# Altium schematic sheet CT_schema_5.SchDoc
size 479 x 328 mm
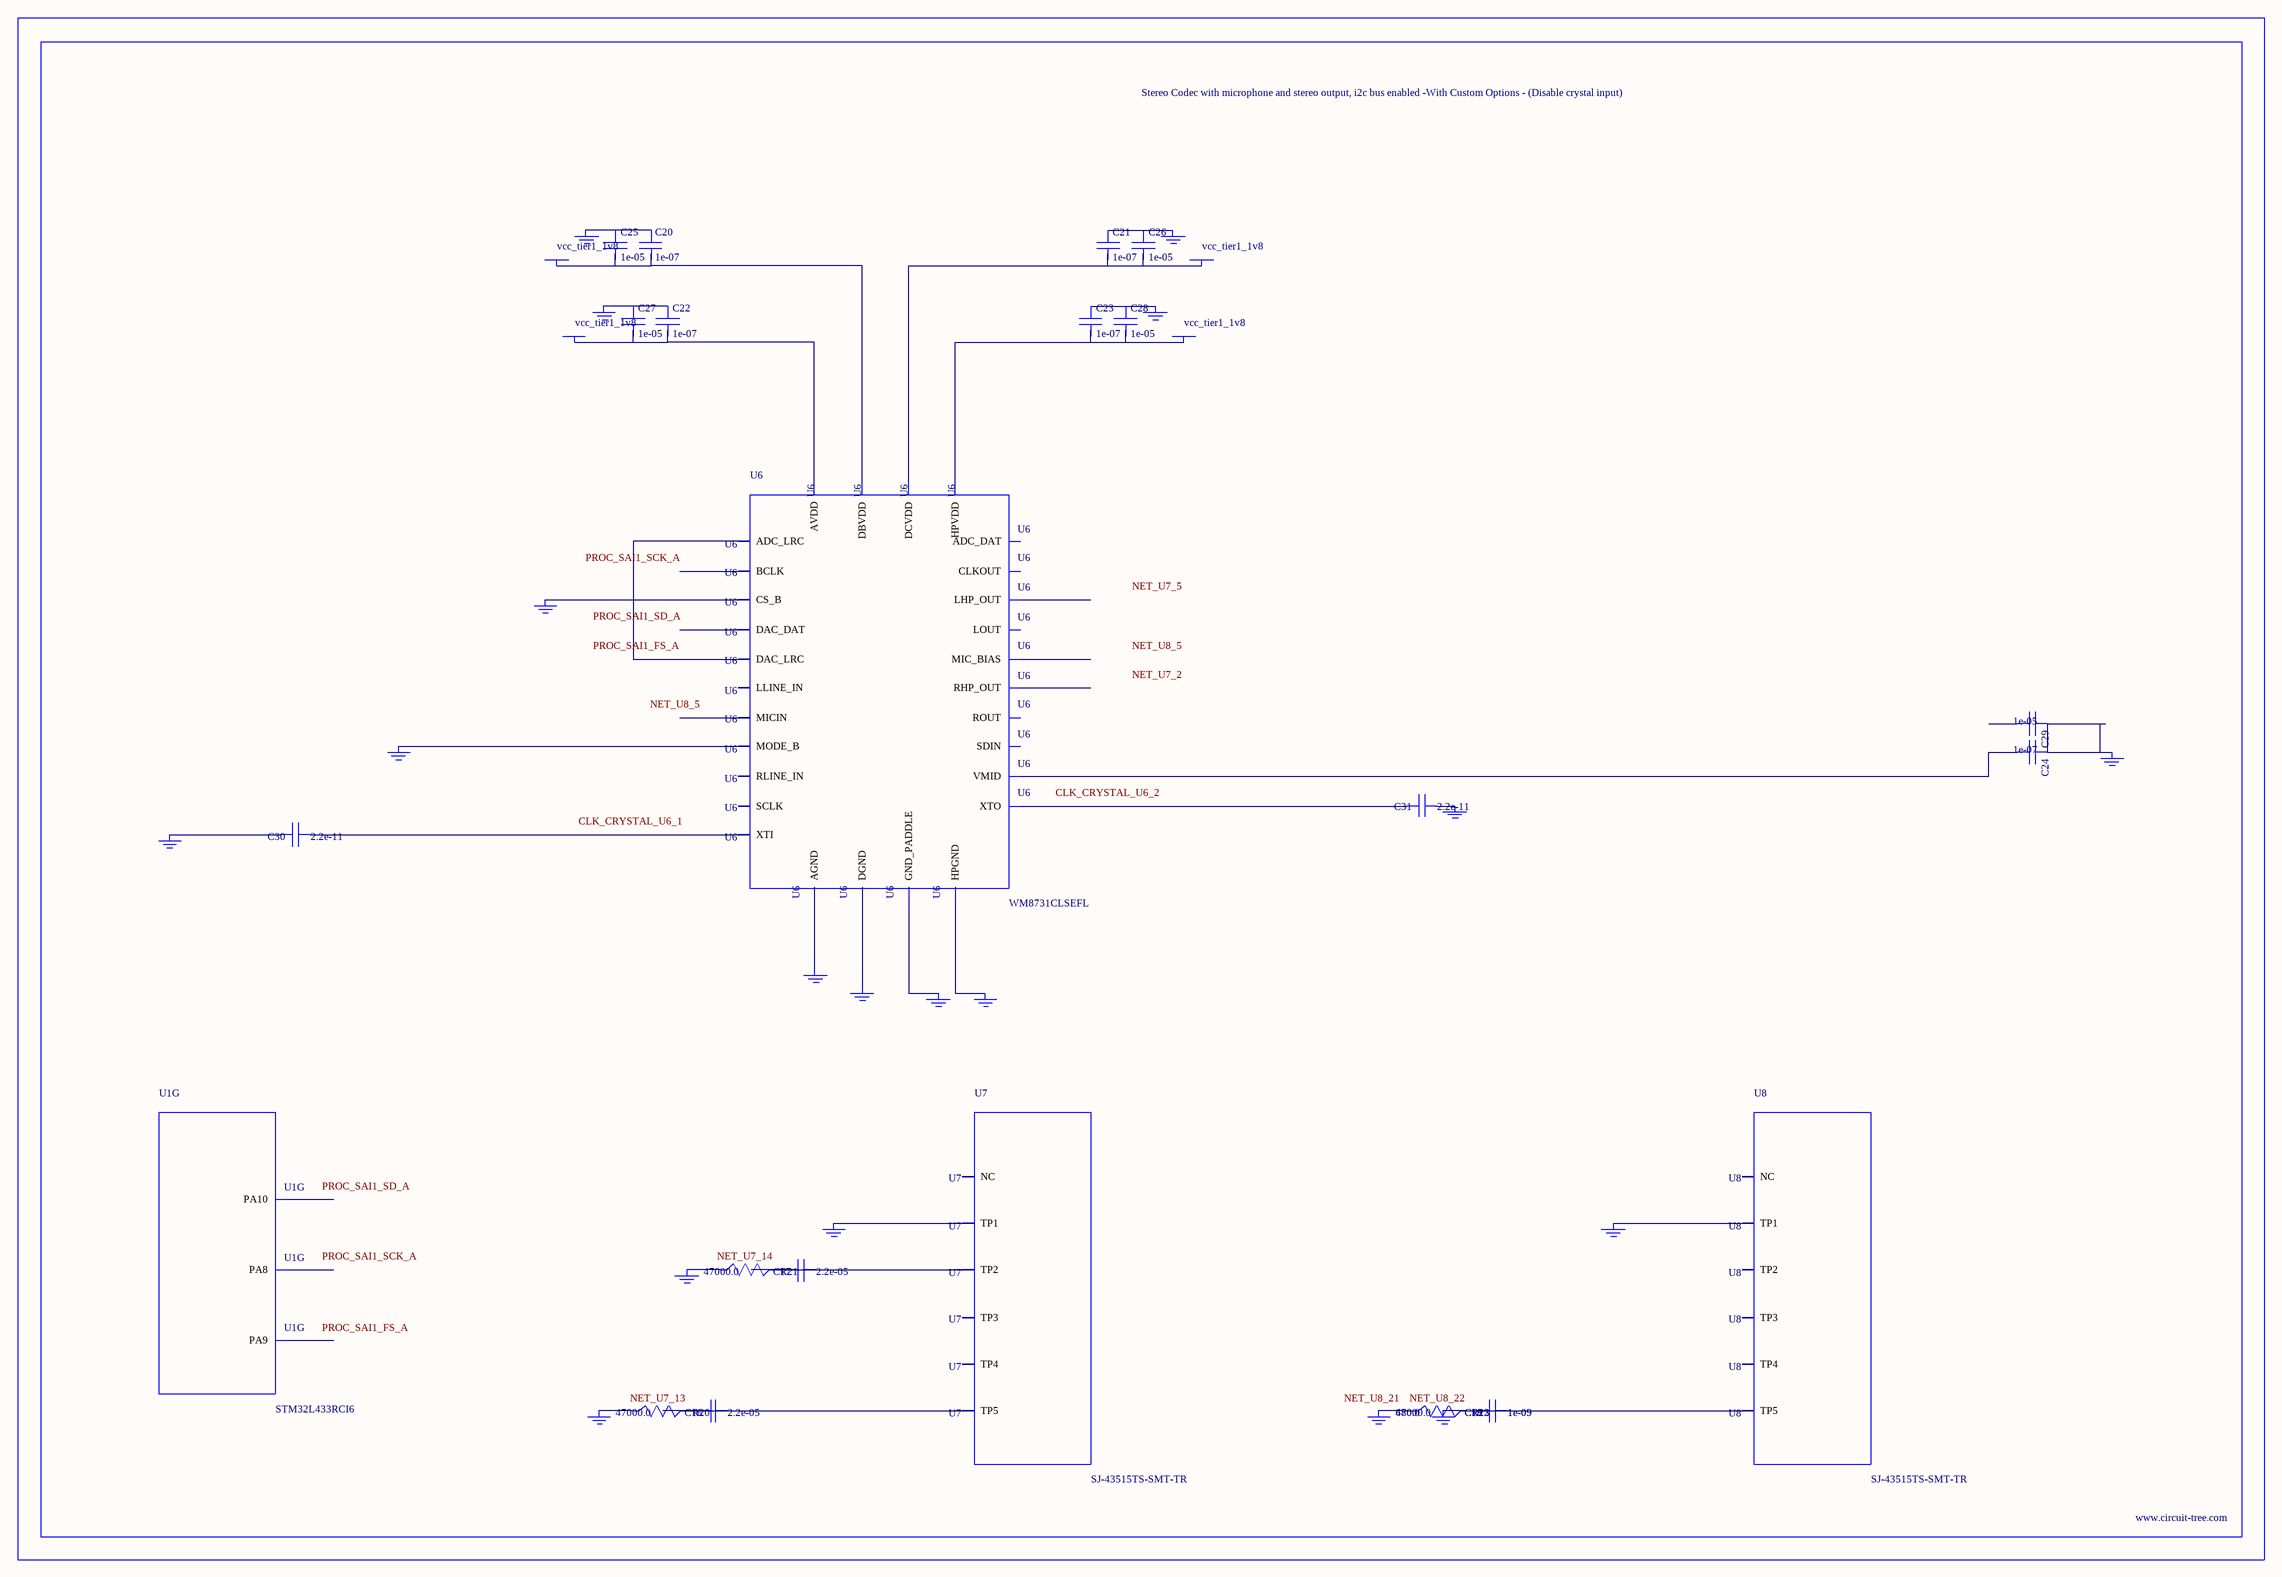
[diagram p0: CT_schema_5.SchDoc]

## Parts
BORDER4  (no value)
C16  2.2e-05  [C1210]
C17  2.2e-05  [C1210]
C18  1e-09  [C0402]
C19  1e-09  [C0402]
C20  1e-07  [C0402]
C21  1e-07  [C0402]
C22  1e-07  [C0402]
C23  1e-07  [C0402]
C24  1e-07  [C0402]
C25  1e-05  [C0805]
C26  1e-05  [C0805]
C27  1e-05  [C0805]
C28  1e-05  [C0805]
C29  1e-05  [C0805]
C30  2.2e-11  [C0402]
C31  2.2e-11  [C0402]
GND_INSTANCE_4_0  (no value)
GND_INSTANCE_4_1  (no value)
GND_INSTANCE_4_2  (no value)
GND_INSTANCE_4_3  (no value)
GND_INSTANCE_4_4  (no value)
GND_INSTANCE_4_5  (no value)
GND_INSTANCE_4_6  (no value)
GND_INSTANCE_4_7  (no value)
GND_INSTANCE_4_8  (no value)
GND_INSTANCE_4_9  (no value)
GND_INSTANCE_4_10  (no value)
GND_INSTANCE_4_11  (no value)
GND_INSTANCE_4_12  (no value)
GND_INSTANCE_4_13  (no value)
GND_INSTANCE_4_14  (no value)
GND_INSTANCE_4_15  (no value)
GND_INSTANCE_4_16  (no value)
GND_INSTANCE_4_17  (no value)
GND_INSTANCE_4_18  (no value)
POWER_INSTANCE_4_0  vcc_tier1_1v8
POWER_INSTANCE_4_1  vcc_tier1_1v8
POWER_INSTANCE_4_2  vcc_tier1_1v8
POWER_INSTANCE_4_3  vcc_tier1_1v8
R20  47000.0  [R0603]
R21  47000.0  [R0603]
R22  47000.0  [R0603]
R23  680.0  [R0603]
U1  STM32L433RCI6  [UFBGA64]  (part G of 7)
U6  WM8731CLSEFL  [QFN-28]
U7  SJ-43515TS-SMT-TR  [SJ-43515TS-SMT-TR]
U8  SJ-43515TS-SMT-TR  [SJ-43515TS-SMT-TR]

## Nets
NetC16_1: C16.1 C16.2 R20.2 U7.5(TP5)
NetC17_1: C17.1 C17.2 R21.2 U7.2(TP2)
NetC18_1: C18.1 C18.2 C19.1 C19.2 GND_INSTANCE_4_18.0(GND) R22.2 R23.2 U8.5(TP5)
NetC20_1: C20.1 C25.1 GND_INSTANCE_4_3.0(GND)
NetC20_2: C20.2 C25.2 POWER_INSTANCE_4_1.0(PWR) U6.5(DBVDD)
NetC21_1: C21.1 C26.1 GND_INSTANCE_4_2.0(GND)
NetC21_2: C21.2 C26.2 POWER_INSTANCE_4_0.0(PWR) U6.3(DCVDD)
NetC22_1: C22.1 C27.1 GND_INSTANCE_4_6.0(GND)
NetC22_2: C22.2 C27.2 POWER_INSTANCE_4_3.0(PWR) U6.18(AVDD)
NetC23_1: C23.1 C28.1 GND_INSTANCE_4_4.0(GND)
NetC23_2: C23.2 C28.2 POWER_INSTANCE_4_2.0(PWR) U6.12(HPVDD)
NetC24_1: C24.1 C29.1 GND_INSTANCE_4_7.0(GND)
NetC24_2: C24.2 U6.20(VMID)
NetC30_1: C30.1 U6.1(XTI)
NetC30_2: C30.2 GND_INSTANCE_4_0.0(GND)
NetC31_1: C31.1 GND_INSTANCE_4_1.0(GND)
NetC31_2: C31.2 U6.2(XTO)
NetGND_INSTANCE_4_5_0: GND_INSTANCE_4_5.0(GND) U6.15(HPGND)
NetGND_INSTANCE_4_8_0: GND_INSTANCE_4_8.0(GND) U6.25(MODE_B)
NetGND_INSTANCE_4_9_0: GND_INSTANCE_4_9.0(GND) U6.26(CS_B)
NetGND_INSTANCE_4_10_0: GND_INSTANCE_4_10.0(GND) U6.29(GND_PADDLE)
NetGND_INSTANCE_4_11_0: GND_INSTANCE_4_11.0(GND) U6.4(DGND)
NetGND_INSTANCE_4_12_0: GND_INSTANCE_4_12.0(GND) U6.19(AGND)
NetGND_INSTANCE_4_13_0: GND_INSTANCE_4_13.0(GND) U7.1(TP1)
NetGND_INSTANCE_4_14_0: GND_INSTANCE_4_14.0(GND) R21.1
NetGND_INSTANCE_4_15_0: GND_INSTANCE_4_15.0(GND) R20.1
NetGND_INSTANCE_4_16_0: GND_INSTANCE_4_16.0(GND) U8.1(TP1)
NetGND_INSTANCE_4_17_0: GND_INSTANCE_4_17.0(GND) R22.1 R23.1
NetU6_9: U6.9(DAC_LRC) U6.11(ADC_LRC)

Not connected (* = marked no-connect by the designer): C29 2; U1 C6(PA10) C7(PA9) D7(PA8); U6 6(CLKOUT) 7(BCLK) 8(DAC_DAT) 10(ADC_DAT) 13(LHP_OUT) 14(RHP_OUT) 16(LOUT) 17(ROUT) 21(MIC_BIAS) 22(MICIN) 23(RLINE_IN) 24(LLINE_IN) 27(SDIN) 28(SCLK); U7 3(TP3) 4(TP4) 6(NC); U8 2(TP2) 3(TP3) 4(TP4) 6(NC)

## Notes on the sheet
- Labels drawn without touching a wire or pin: CLK_CRYSTAL_U6_1, CLK_CRYSTAL_U6_2, NET_U7_2, NET_U7_5, NET_U7_13, NET_U7_14, NET_U8_5, NET_U8_21, NET_U8_22, PROC_SAI1_FS_A, PROC_SAI1_SCK_A, PROC_SAI1_SD_A

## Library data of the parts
BORDER4 = BORDER_PAGE4
C16 C17 = C1210C224K5RACTU
C18 C19 = C0402C102K3RAC
C20-C24 = C0402C104K3RACTU
C25-C29 = C0805C106K8RACTU
C30 C31 = C0402C220K3RAC
GND_INSTANCE_4_0-GND_INSTANCE_4_18 = GND
POWER_INSTANCE_4_0-POWER_INSTANCE_4_3 = PWR
R20-R22 = RC0603JR-0747KL
R23 = RC0603JR-07680RL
